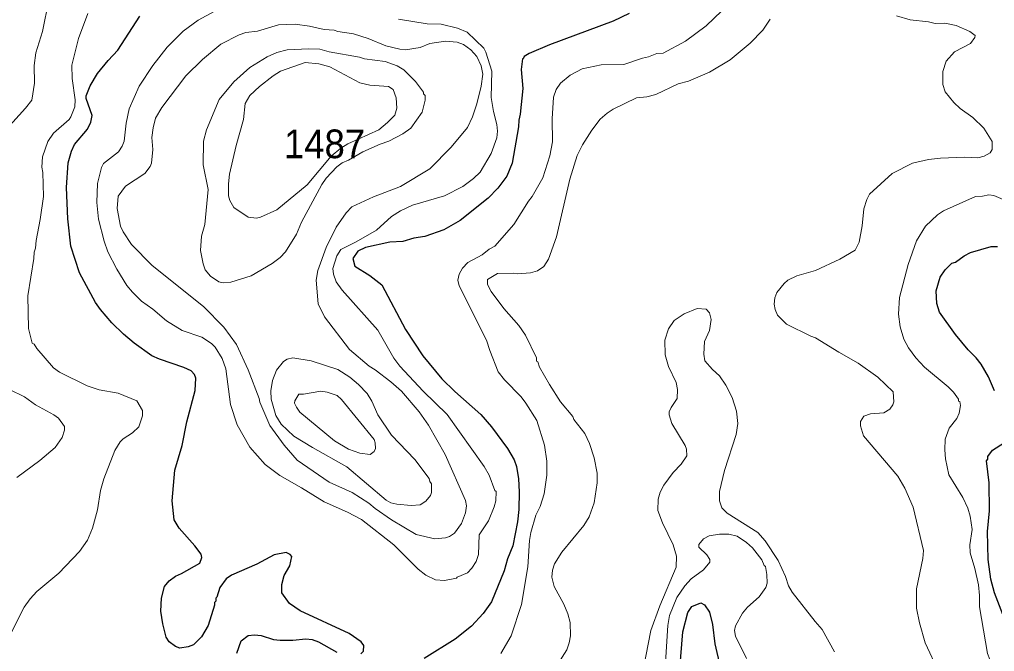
# Model space of a CAD drawing. Extents: x 598.3 to 623.2, y 6902.2 to 6930.1.
# Drawn here: x 610.873 to 613.593, y 6903.785 to 6905.547 of the extents above; entities that cross this region are included whole.
import ezdxf

# ---------------------------------------------------------------- set-up
doc = ezdxf.new("R2010")
doc.units = 0
doc.header["$LTSCALE"] = 0.032
doc.layers.add('1', color=7, linetype='Continuous', lineweight=25)
doc.layers.add('2', color=7, linetype='Continuous', lineweight=13)
doc.layers.add('21', color=7, linetype='Continuous')

msp = doc.modelspace()

# ---------------------------------------------------------------- linework, layer by layer
at = {"layer": '1'}
for points in [[(612.5734, 6905.5642), (612.5291, 6905.5421), (612.3514, 6905.4768)], [(611.6266, 6903.9183), (611.6049, 6903.9481), (611.605, 6903.9719), (611.6112, 6903.9967), (611.6275, 6904.0238), (611.6325, 6904.0497), (611.6278, 6904.0553), (611.6174, 6904.0611), (611.5839, 6904.0547), (611.5348, 6904.0285), (611.4642, 6903.9972), (611.4498, 6903.9869), (611.4319, 6903.9627), (611.4237, 6903.9363), (611.4205, 6903.9338), (611.4204, 6903.9255), (611.4173, 6903.9217), (611.4171, 6903.9137), (611.3994, 6903.8572), (611.3804, 6903.8254), (611.3588, 6903.8031), (611.3438, 6903.7974), (611.3201, 6903.7941), (611.3085, 6903.7983), (611.2903, 6903.8118), (611.2824, 6903.8246), (611.2731, 6903.8621), (611.2675, 6903.897), (611.269, 6903.933), (611.278, 6903.9657), (611.2904, 6903.9821), (611.3081, 6903.9952), (611.3249, 6904.0021), (611.3759, 6904.0313), (611.3815, 6904.0471), (611.3798, 6904.0565), (611.3627, 6904.0793), (611.3182, 6904.1286), (611.3049, 6904.1517), (611.2991, 6904.2046), (611.3063, 6904.2908), (611.3266, 6904.3594), (611.3402, 6904.4251), (611.3629, 6904.5129), (611.3653, 6904.5472), (611.3612, 6904.5575), (611.3518, 6904.5677), (611.3315, 6904.5771), (611.2635, 6904.5999), (611.2426, 6904.6091), (611.1928, 6904.6442), (611.163, 6904.6694), (611.1308, 6904.7012), (611.0988, 6904.738), (611.0852, 6904.7577), (611.0406, 6904.8406), (611.0165, 6904.9146), (611.0077, 6904.9915), (611.0044, 6905.0786), (611.0092, 6905.1472), (611.0181, 6905.1799), (611.0268, 6905.1981), (611.0628, 6905.2409), (611.0724, 6905.2612), (611.0755, 6905.2789), (611.0595, 6905.3269), (611.0595, 6905.3345), (611.0706, 6905.3625), (611.0912, 6905.3963), (611.1206, 6905.4331), (611.1478, 6905.4619), (611.2093, 6905.5566)], [(612.3514, 6905.4768), (612.2947, 6905.4527), (612.281, 6905.4438), (612.2785, 6905.4377), (612.276, 6905.437), (612.2721, 6905.4075), (612.2768, 6905.3545), (612.2695, 6905.2835), (612.2656, 6905.266), (612.2655, 6905.2476), (612.247, 6905.1462), (612.2328, 6905.1098), (612.207, 6905.0769), (612.18, 6905.0492), (612.1025, 6904.9868), (612.0572, 6904.9606), (612.0035, 6904.942), (611.9735, 6904.937), (611.942, 6904.9283), (611.9058, 6904.9257), (611.8384, 6904.9113), (611.8171, 6904.9014), (611.8026, 6904.8809), (611.8085, 6904.8593), (611.8501, 6904.8328), (611.8836, 6904.8072), (611.9499, 6904.6823), (611.9986, 6904.609), (612.0516, 6904.5448), (612.0877, 6904.5095), (612.1599, 6904.4452), (612.1896, 6904.4115), (612.2342, 6904.3508), (612.2533, 6904.3189), (612.2591, 6904.3005), (612.2646, 6904.2665), (612.2671, 6904.2299), (612.2663, 6904.1807), (612.2623, 6904.1467), (612.2494, 6904.0793), (612.2347, 6904.0431), (612.2251, 6904.0097), (612.1893, 6903.9234), (612.1664, 6903.891), (612.1338, 6903.8557), (612.0888, 6903.819), (612.0016, 6903.7649)], [(613.484, 6904.8708), (613.5079, 6904.8876), (613.5258, 6904.8969), (613.5831, 6904.9136), (613.6015, 6904.9144)], [(613.593, 6904.5116), (613.576, 6904.5504), (613.5558, 6904.5862), (613.5418, 6904.6038), (613.5189, 6904.626), (613.4838, 6904.6684), (613.4398, 6904.7308), (613.4321, 6904.7548), (613.4297, 6904.79), (613.441, 6904.8286), (613.4552, 6904.8486), (613.4733, 6904.8674), (613.484, 6904.8708)], [(613.616, 6903.8876), (613.5923, 6903.9479), (613.5825, 6903.9867), (613.5754, 6904.0411), (613.5736, 6904.1195), (613.5785, 6904.1771), (613.5777, 6904.2553), (613.5705, 6904.316), (613.5737, 6904.3208), (613.5746, 6904.3286), (613.5869, 6904.3463), (613.6208, 6904.3676)], [(611.8249, 6903.7786), (611.8327, 6903.7858), (611.8337, 6903.801), (611.8266, 6903.8121), (611.7931, 6903.8352), (611.6565, 6903.898), (611.6266, 6903.9183)], [(612.7123, 6903.7015), (612.7237, 6903.8391), (612.7377, 6903.8931), (612.7488, 6903.9105), (612.7733, 6903.9202), (612.7841, 6903.9149), (612.7982, 6903.8944), (612.8062, 6903.8604), (612.8131, 6903.8065), (612.8274, 6903.742)], [(611.4794, 6903.7803), (611.4917, 6903.8142), (611.5106, 6903.8294), (611.5286, 6903.8313), (611.547, 6903.8297), (611.5816, 6903.8185), (611.6004, 6903.8159), (611.6355, 6903.8159), (611.6717, 6903.8199), (611.6892, 6903.8183), (611.7073, 6903.8118), (611.7583, 6903.7826)]]:
    msp.add_lwpolyline(points, dxfattribs=at)
at = {"layer": '2'}
for points in [[(610.9549, 6905.6011), (610.9372, 6905.5137), (610.9191, 6905.4542), (610.9138, 6905.4185), (610.9153, 6905.3691), (610.9072, 6905.3224), (610.89, 6905.2995), (610.8367, 6905.2412)], [(610.8967, 6904.7768), (610.913, 6904.8807), (610.9138, 6904.8986), (610.9178, 6904.9092), (610.9194, 6904.9312), (610.9307, 6904.9889), (610.9398, 6905.0535), (610.938, 6905.1206), (610.9356, 6905.1357), (610.9378, 6905.1644), (610.9521, 6905.2067), (610.9681, 6905.2303), (611.0116, 6905.2681), (611.0166, 6905.2757), (611.0271, 6905.3033), (611.0286, 6905.323), (611.0198, 6905.3821), (611.0194, 6905.4195), (611.0379, 6905.4938), (611.0642, 6905.5636)], [(611.428, 6905.5763), (611.3712, 6905.5451), (611.3294, 6905.5146), (611.2848, 6905.4701), (611.2455, 6905.419), (611.2074, 6905.361), (611.1788, 6905.2975), (611.1703, 6905.2576), (611.1654, 6905.2074), (611.1593, 6905.1934), (611.1492, 6905.1784), (611.1072, 6905.1451), (611.1022, 6905.1342), (611.0908, 6905.09), (611.0886, 6905.0369), (611.094, 6904.9899), (611.1096, 6904.9288), (611.1196, 6904.8993), (611.1449, 6904.8504), (611.1729, 6904.8057), (611.1883, 6904.7863), (611.2132, 6904.7614), (611.2454, 6904.7389), (611.2831, 6904.7067), (611.327, 6904.6802), (611.3819, 6904.6609), (611.4086, 6904.6433), (611.419, 6904.6333), (611.4381, 6904.6022), (611.4488, 6904.5726), (611.4615, 6904.4734), (611.4806, 6904.4169), (611.5158, 6904.3545), (611.5586, 6904.3058), (611.5993, 6904.2757), (611.6598, 6904.2411), (611.7227, 6904.2023), (611.7885, 6904.1735), (611.8268, 6904.1526), (611.9177, 6904.0821), (611.9848, 6904.014), (612.007, 6903.9977), (612.0335, 6903.9845), (612.0589, 6903.9831), (612.0921, 6903.9892), (612.0938, 6903.9918), (612.1229, 6904.0044), (612.1351, 6904.0173), (612.1468, 6904.0359), (612.1539, 6904.055), (612.1555, 6904.1097), (612.181, 6904.1495), (612.1976, 6904.1878), (612.2018, 6904.2051), (612.2024, 6904.231), (612.1991, 6904.2333), (612.1828, 6904.2768), (612.1691, 6904.301), (612.066, 6904.4454), (611.9988, 6904.5109), (611.934, 6904.5806)], [(612.3528, 6905.1666), (612.3595, 6905.2061), (612.3587, 6905.2699), (612.3627, 6905.3308), (612.3698, 6905.3514), (612.3821, 6905.3693), (612.4096, 6905.392), (612.4427, 6905.4095), (612.4957, 6905.4203), (612.5591, 6905.422), (612.6105, 6905.4397), (612.6276, 6905.4425), (612.651, 6905.4519), (612.6687, 6905.4529), (612.7307, 6905.4862), (612.7887, 6905.5298), (612.8319, 6905.5714)], [(611.7729, 6904.7926), (611.7569, 6904.8155), (611.7486, 6904.8369), (611.7474, 6904.8525), (611.7586, 6904.888), (611.7693, 6904.9061), (611.812, 6904.9272), (611.8687, 6904.9596), (611.9104, 6904.9975), (611.9356, 6905.0132), (611.9696, 6905.0294), (612.0582, 6905.0551), (612.1095, 6905.0816), (612.1399, 6905.1036), (612.1578, 6905.1214), (612.1885, 6905.1732), (612.2048, 6905.2171), (612.2064, 6905.2361), (612.2049, 6905.2542), (612.1951, 6905.2903), (612.1885, 6905.3299), (612.1903, 6905.4028), (612.1743, 6905.4563), (612.1682, 6905.4668), (612.1222, 6905.5118), (612.095, 6905.5233), (612.0489, 6905.5336), (612.0107, 6905.5352), (611.9307, 6905.5482)], [(612.9669, 6905.5477), (612.9465, 6905.5176), (612.9116, 6905.4812), (612.8555, 6905.4343), (612.798, 6905.4001), (612.7393, 6905.3754), (612.7101, 6905.3673), (612.6485, 6905.3381), (612.6231, 6905.3313), (612.5945, 6905.3289), (612.5292, 6905.2972), (612.5121, 6905.2858), (612.493, 6905.2689), (612.4694, 6905.238), (612.4435, 6905.1975), (612.4288, 6905.1681), (612.408, 6905.1022)], [(613.4377, 6903.7275), (613.3996, 6903.8093), (613.3832, 6903.8646), (613.375, 6903.9057), (613.3752, 6903.9599), (613.3932, 6904.0437), (613.3948, 6904.0665), (613.3658, 6904.187), (613.3424, 6904.2405), (613.3227, 6904.2733), (613.2276, 6904.3861), (613.2192, 6904.4136), (613.2192, 6904.4261), (613.2282, 6904.4407), (613.2472, 6904.4474), (613.2844, 6904.4506), (613.301, 6904.4605), (613.3096, 6904.4726), (613.3115, 6904.4808), (613.31, 6904.509), (613.2673, 6904.5497), (613.2126, 6904.5889), (613.1582, 6904.6194), (613.0939, 6904.6593), (613.0807, 6904.6638), (613.013, 6904.6973), (612.9879, 6904.7223), (612.9811, 6904.7382), (612.9779, 6904.7535), (612.9796, 6904.7706), (612.9852, 6904.7856), (613.0057, 6904.8111), (613.0167, 6904.8205), (613.041, 6904.8326), (613.0931, 6904.8474), (613.1617, 6904.8791), (613.2044, 6904.904), (613.2151, 6904.926), (613.224, 6904.9714), (613.2286, 6905.0187), (613.2365, 6905.0448), (613.2441, 6905.0599), (613.307, 6905.1172), (613.3644, 6905.1467), (613.4088, 6905.1565), (613.442, 6905.1605), (613.5095, 6905.163), (613.5464, 6905.1614), (613.5643, 6905.1662), (613.581, 6905.1751), (613.5858, 6905.1848), (613.5866, 6905.2064), (613.5627, 6905.2443), (613.5322, 6905.274), (613.4971, 6905.2993), (613.4791, 6905.3157), (613.4556, 6905.3456), (613.4491, 6905.3656), (613.449, 6905.4017), (613.4578, 6905.4307), (613.4812, 6905.4565), (613.5259, 6905.4804), (613.5376, 6905.4967), (613.5387, 6905.5029), (613.5243, 6905.5134), (613.486, 6905.5305), (613.4542, 6905.5369), (613.4272, 6905.5362), (613.4085, 6905.5409), (613.3573, 6905.5463), (613.3195, 6905.5572)], [(612.2155, 6903.7795), (612.2446, 6903.8286), (612.2734, 6903.9162), (612.2915, 6904.021), (612.2959, 6904.0941), (612.2995, 6904.1162), (612.3133, 6904.1646), (612.3252, 6904.1886), (612.3367, 6904.2245), (612.344, 6904.276), (612.3441, 6904.315), (612.3377, 6904.3605), (612.3158, 6904.4285), (612.2857, 6904.4773), (612.2724, 6904.4947), (612.2259, 6904.5422), (612.2087, 6904.5642), (612.1849, 6904.6237), (612.176, 6904.6532), (612.0992, 6904.8046), (612.0963, 6904.8201), (612.0997, 6904.8366), (612.1092, 6904.8533), (612.1234, 6904.8695), (612.1633, 6904.8908), (612.1836, 6904.907), (612.199, 6904.9151), (612.2519, 6904.9753), (612.2931, 6905.0404), (612.3035, 6905.0531), (612.3332, 6905.1059), (612.3528, 6905.1666)], [(612.408, 6905.1022), (612.3713, 6904.941), (612.3488, 6904.8787), (612.3353, 6904.858), (612.3182, 6904.846), (612.2987, 6904.8408), (612.261, 6904.8376), (612.2509, 6904.8398), (612.2069, 6904.8384), (612.1789, 6904.8224), (612.1782, 6904.8078), (612.1884, 6904.7889), (612.2244, 6904.741), (612.2659, 6904.6938), (612.2843, 6904.6665), (612.3148, 6904.6036), (612.3157, 6904.5941), (612.319, 6904.592), (612.324, 6904.5775), (612.3515, 6904.5289), (612.3825, 6904.4808), (612.4167, 6904.4402), (612.4197, 6904.432), (612.4504, 6904.3926), (612.4635, 6904.3649), (612.4762, 6904.3246), (612.4841, 6904.2817), (612.4849, 6904.255), (612.4761, 6904.1991), (612.4621, 6904.1598), (612.447, 6904.1359), (612.386, 6904.0618), (612.3654, 6904.0294), (612.3595, 6904.0116), (612.3579, 6903.9917), (612.3647, 6903.9664), (612.3913, 6903.9166), (612.4024, 6903.8894), (612.4089, 6903.8651), (612.4097, 6903.8284), (612.4064, 6903.8089), (612.3998, 6903.789), (612.376, 6903.7509)], [(613.6169, 6905.045), (613.5913, 6905.0561), (613.5773, 6905.0578), (613.5594, 6905.0545), (613.54, 6905.0536), (613.4506, 6905.0139), (613.4337, 6905.0028), (613.4006, 6904.9712), (613.3749, 6904.9299), (613.3518, 6904.8642), (613.3276, 6904.7722), (613.3251, 6904.7254), (613.3294, 6904.6905), (613.3401, 6904.6554), (613.3525, 6904.6314), (613.3731, 6904.6033), (613.3978, 6904.5779), (613.4632, 6904.523), (613.4785, 6904.5077), (613.4926, 6904.4885), (613.4928, 6904.4832), (613.496, 6904.4815), (613.4975, 6904.4703), (613.4941, 6904.4492)], [(610.8425, 6903.8219), (610.8858, 6903.9085), (610.9025, 6903.9311), (610.9214, 6903.9516), (610.9827, 6904.0031), (611.0408, 6904.064), (611.0633, 6904.095), (611.0767, 6904.1285), (611.091, 6904.1797), (611.0991, 6904.2334), (611.1083, 6904.2666), (611.1393, 6904.3456), (611.154, 6904.3692), (611.1624, 6904.3779), (611.1882, 6904.3946), (611.2058, 6904.4116), (611.2164, 6904.4417), (611.2164, 6904.4568), (611.2002, 6904.4837), (611.1484, 6904.5048), (611.095, 6904.5145), (611.0621, 6904.5255), (610.9844, 6904.5638), (610.9684, 6904.5757), (610.9211, 6904.6293), (610.9137, 6904.6415), (610.9088, 6904.6443), (610.8982, 6904.6854), (610.8967, 6904.7768)], [(611.934, 6904.5806), (611.9169, 6904.6028), (611.8723, 6904.6811), (611.7729, 6904.7926)], [(612.6134, 6903.7384), (612.6343, 6903.8433), (612.6596, 6903.9121), (612.7051, 6904.0203), (612.7059, 6904.0502), (612.696, 6904.0825), (612.6665, 6904.1432), (612.6534, 6904.1779), (612.6547, 6904.2092), (612.6604, 6904.2294), (612.6703, 6904.2482), (612.6966, 6904.2841), (612.7192, 6904.3068), (612.735, 6904.3303), (612.7335, 6904.3492), (612.73, 6904.3594), (612.6932, 6904.4201), (612.6857, 6904.4444), (612.6857, 6904.4529), (612.691, 6904.4652), (612.7074, 6904.49), (612.7083, 6904.5151), (612.7048, 6904.5349), (612.6839, 6904.5796), (612.6738, 6904.6123), (612.6736, 6904.6527), (612.6839, 6904.6843), (612.6995, 6904.708), (612.7275, 6904.7265), (612.7636, 6904.7412), (612.7883, 6904.7394), (612.7976, 6904.7293), (612.8022, 6904.7107), (612.7974, 6904.6799), (612.7839, 6904.6495), (612.7821, 6904.614), (612.7852, 6904.5956), (612.8059, 6904.5708), (612.8253, 6904.5531), (612.8434, 6904.5278), (612.8607, 6904.4929), (612.8734, 6904.4546), (612.8767, 6904.4204), (612.8719, 6904.3902), (612.8394, 6904.2895), (612.826, 6904.2306), (612.8258, 6904.2051), (612.8322, 6904.1853), (612.8467, 6904.17), (612.9324, 6904.1164), (612.9527, 6904.0931), (612.9894, 6904.0383), (613.0101, 6903.9935), (613.0186, 6903.9679), (613.0283, 6903.9504)], [(610.8455, 6904.5154), (610.8876, 6904.4944), (610.9182, 6904.4729), (610.9693, 6904.445), (610.9823, 6904.4353), (610.9987, 6904.4125), (610.999, 6904.4017), (610.9926, 6904.381), (610.9724, 6904.3531), (610.9303, 6904.3175), (610.8653, 6904.2701)], [(613.4941, 6904.4492), (613.4879, 6904.4346), (613.4659, 6904.4075), (613.4556, 6904.3772), (613.4538, 6904.3468), (613.4557, 6904.3218), (613.4655, 6904.2776), (613.5047, 6904.2137), (613.5184, 6904.1848), (613.525, 6904.1622), (613.53, 6904.125), (613.5244, 6904.0825), (613.5251, 6904.0599), (613.5379, 6904.0165), (613.5478, 6903.9703), (613.551, 6903.9404), (613.5512, 6903.9089), (613.573, 6903.7789), (613.5865, 6903.7458), (613.6194, 6903.6856)], [(612.9009, 6903.7652), (612.8706, 6903.8279), (612.8679, 6903.8434), (612.8699, 6903.8566), (612.8895, 6903.8916), (612.904, 6903.908), (612.936, 6903.9367), (612.9549, 6903.9627), (612.9584, 6903.9752), (612.9577, 6903.9992), (612.9536, 6904.022), (612.9504, 6904.0242), (612.9438, 6904.0402), (612.9173, 6904.074), (612.9008, 6904.0889), (612.8754, 6904.1067), (612.8519, 6904.1122), (612.8257, 6904.1123), (612.7969, 6904.1074), (612.7809, 6904.0987), (612.7684, 6904.0833), (612.7681, 6904.0755), (612.7901, 6904.0539), (612.799, 6904.0415), (612.799, 6904.034), (612.7809, 6904.0123), (612.7467, 6903.9869), (612.7293, 6903.9681), (612.7066, 6903.9355), (612.6865, 6903.885), (612.682, 6903.8568), (612.6719, 6903.7097)], [(613.0283, 6903.9504), (613.0924, 6903.868), (613.1122, 6903.8459), (613.1462, 6903.784)]]:
    msp.add_lwpolyline(points, dxfattribs=at)
for points in [[(611.7009, 6904.8201), (611.7052, 6904.8471), (611.7282, 6904.9115), (611.7562, 6904.9676), (611.7843, 6905.0079), (611.7999, 6905.0243), (611.8603, 6905.0526), (611.9356, 6905.0813), (612.0182, 6905.131), (612.0775, 6905.191), (612.123, 6905.2461), (612.1368, 6905.2757), (612.1491, 6905.3117), (612.161, 6905.3607), (612.1659, 6905.3942), (612.1612, 6905.4177), (612.1491, 6905.4436), (612.1324, 6905.4628), (612.112, 6905.4777), (612.0939, 6905.4834), (612.0615, 6905.4867), (612.0181, 6905.4803), (611.9906, 6905.469), (611.9501, 6905.4625), (611.9336, 6905.464), (611.8948, 6905.4734), (611.8455, 6905.4945), (611.8044, 6905.5069), (611.7615, 6905.5135), (611.7506, 6905.5174), (611.7227, 6905.5192), (611.6825, 6905.5281), (611.6425, 6905.5336), (611.5953, 6905.532), (611.5373, 6905.5143), (611.5047, 6905.511), (611.4863, 6905.5043), (611.4345, 6905.4785), (611.3832, 6905.4358), (611.3374, 6905.39), (611.2702, 6905.3018), (611.2527, 6905.272), (611.2456, 6905.2453), (611.2423, 6905.2184), (611.2455, 6905.1843), (611.2416, 6905.1465), (611.2377, 6905.1368), (611.2231, 6905.1178), (611.1684, 6905.0822), (611.1483, 6905.054), (611.1457, 6905.0197), (611.1551, 6904.9706), (611.1621, 6904.9552), (611.1855, 6904.9192), (611.2429, 6904.8612), (611.3861, 6904.7472), (611.4427, 6904.689), (611.4781, 6904.6406), (611.5107, 6904.5704), (611.5419, 6904.49), (611.5438, 6904.4796), (611.5713, 6904.4153), (611.6118, 6904.3603), (611.648, 6904.3178), (611.7366, 6904.2569), (611.8012, 6904.2278), (611.8474, 6904.1984), (611.8655, 6904.1834), (611.911, 6904.1523), (611.9798, 6904.111), (612.0319, 6904.0993), (612.0618, 6904.1017), (612.0728, 6904.1056), (612.0868, 6904.1148), (612.1063, 6904.1412), (612.1175, 6904.1716), (612.1198, 6904.1905), (612.1175, 6904.2059), (612.0602, 6904.3343), (612.0142, 6904.4159), (611.9882, 6904.4526), (611.9384, 6904.5105), (611.9088, 6904.5371), (611.8656, 6904.5703), (611.8483, 6904.5806), (611.7932, 6904.6267), (611.7242, 6904.7183), (611.7063, 6904.7545)], [(611.5193, 6904.8326), (611.5783, 6904.8666), (611.6003, 6904.8838), (611.615, 6904.899), (611.6457, 6904.9489), (611.6597, 6904.9817), (611.7166, 6905.0874), (611.7282, 6905.105), (611.758, 6905.1362), (611.7732, 6905.1474), (611.7905, 6905.1545), (611.8311, 6905.178), (611.8795, 6905.1997), (611.9038, 6905.2078), (611.9426, 6905.2281), (611.9646, 6905.244), (611.9968, 6905.2889), (612.0049, 6905.3224), (612.0049, 6905.3351), (612.0004, 6905.3399), (612, 6905.3447), (611.978, 6905.3744), (611.9448, 6905.4068), (611.9264, 6905.4183), (611.8935, 6905.43), (611.8354, 6905.4378), (611.8214, 6905.4422), (611.7371, 6905.4565), (611.7105, 6905.464), (611.6798, 6905.4657), (611.6199, 6905.4625), (611.5914, 6905.4547), (611.5639, 6905.4427), (611.5157, 6905.4129), (611.4714, 6905.3734), (611.4304, 6905.3238), (611.3945, 6905.2398), (611.3865, 6905.208), (611.3852, 6905.1414), (611.3993, 6905.0729), (611.3905, 6904.9757), (611.3807, 6904.9433), (611.3776, 6904.9029), (611.3856, 6904.8658), (611.3915, 6904.8494), (611.4057, 6904.8312), (611.4288, 6904.8157), (611.4414, 6904.8125), (611.4631, 6904.8149)], [(611.5341, 6904.993), (611.5454, 6904.9954), (611.5913, 6905.0162), (611.6758, 6905.0864), (611.7429, 6905.1657), (611.7693, 6905.1882), (611.7892, 6905.2004), (611.8752, 6905.2397), (611.8998, 6905.2594), (611.9197, 6905.2801), (611.9255, 6905.2997), (611.924, 6905.3287), (611.9158, 6905.3523), (611.9026, 6905.3604), (611.8506, 6905.3637), (611.8225, 6905.37), (611.7392, 6905.4147), (611.7084, 6905.4236), (611.6704, 6905.4267), (611.6013, 6905.403), (611.5807, 6905.3903), (611.5422, 6905.3601), (611.5161, 6905.3347), (611.503, 6905.3125), (611.4982, 6905.268), (611.4771, 6905.1961), (611.459, 6905.1159), (611.4561, 6905.0886), (611.4561, 6905.0551), (611.4599, 6905.0425), (611.4708, 6905.0228), (611.5109, 6904.9963)], [(611.6871, 6904.5948), (611.7607, 6904.5711), (611.7942, 6904.5495), (611.8191, 6904.5291), (611.8425, 6904.5037), (611.8558, 6904.4824), (611.8726, 6904.4445), (611.9109, 6904.3883), (611.9761, 6904.3198), (612.0161, 6904.2667), (612.0174, 6904.2588), (612.0227, 6904.2519), (612.022, 6904.2283), (612.0194, 6904.2199), (612.0065, 6904.2037), (611.9906, 6904.194), (611.9655, 6904.1916), (611.9254, 6904.1957), (611.9094, 6904.1997), (611.8959, 6904.2063), (611.7863, 6904.3), (611.6905, 6904.3537), (611.6386, 6904.3855), (611.6035, 6904.4188), (611.5883, 6904.4428), (611.5755, 6904.4885), (611.5738, 6904.5118), (611.5792, 6904.5404), (611.5903, 6904.5694), (611.6098, 6904.5936), (611.6201, 6904.5997), (611.6356, 6904.6035)], [(611.7711, 6904.4876), (611.7596, 6904.4983), (611.7316, 6904.508), (611.7135, 6904.5104), (611.6652, 6904.5024), (611.6522, 6904.5023), (611.6408, 6904.4838), (611.6407, 6904.4774), (611.6456, 6904.4659), (611.6555, 6904.4519), (611.7519, 6904.3724), (611.7912, 6904.3485), (611.8225, 6904.3374), (611.8515, 6904.3342), (611.8626, 6904.3423), (611.8658, 6904.3507), (611.8653, 6904.3666), (611.8623, 6904.3756)]]:
    msp.add_lwpolyline(points, close=True, dxfattribs=at)

# ---------------------------------------------------------------- texts
at = {"layer": '21', "width": 0.95}
msp.add_text('1487', height=0.08, dxfattribs=at).set_placement((611.611, 6905.1603))

doc.saveas('drawing.dxf')
